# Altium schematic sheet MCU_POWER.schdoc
size 297 x 209 mm; Symbol: Drawing-Symbol_A4; Company: 嘉立创EDA; Version: V1.0; Page Size: A4; @Project Name: 西柚在学EtherCAT; @Update Date: 2026-07-29; @Create Date: 2026-07-29; Device: Drawing-Symbol_A4; @Board Name: Board1; @Page Name: P1; @Create Time: 01:18:30; @Page Count: 1; @Page No: 1; @Schematic Name: Schematic1; @Update Time: 01:18:30; @Assembly Variant: Basic; Border: 1; Title Block Position: 3; Size: A4; Width: 1170; Height: 825; Region Start: 1; X Region Count: 6; Y Region Count: 4; Blade Width: 10
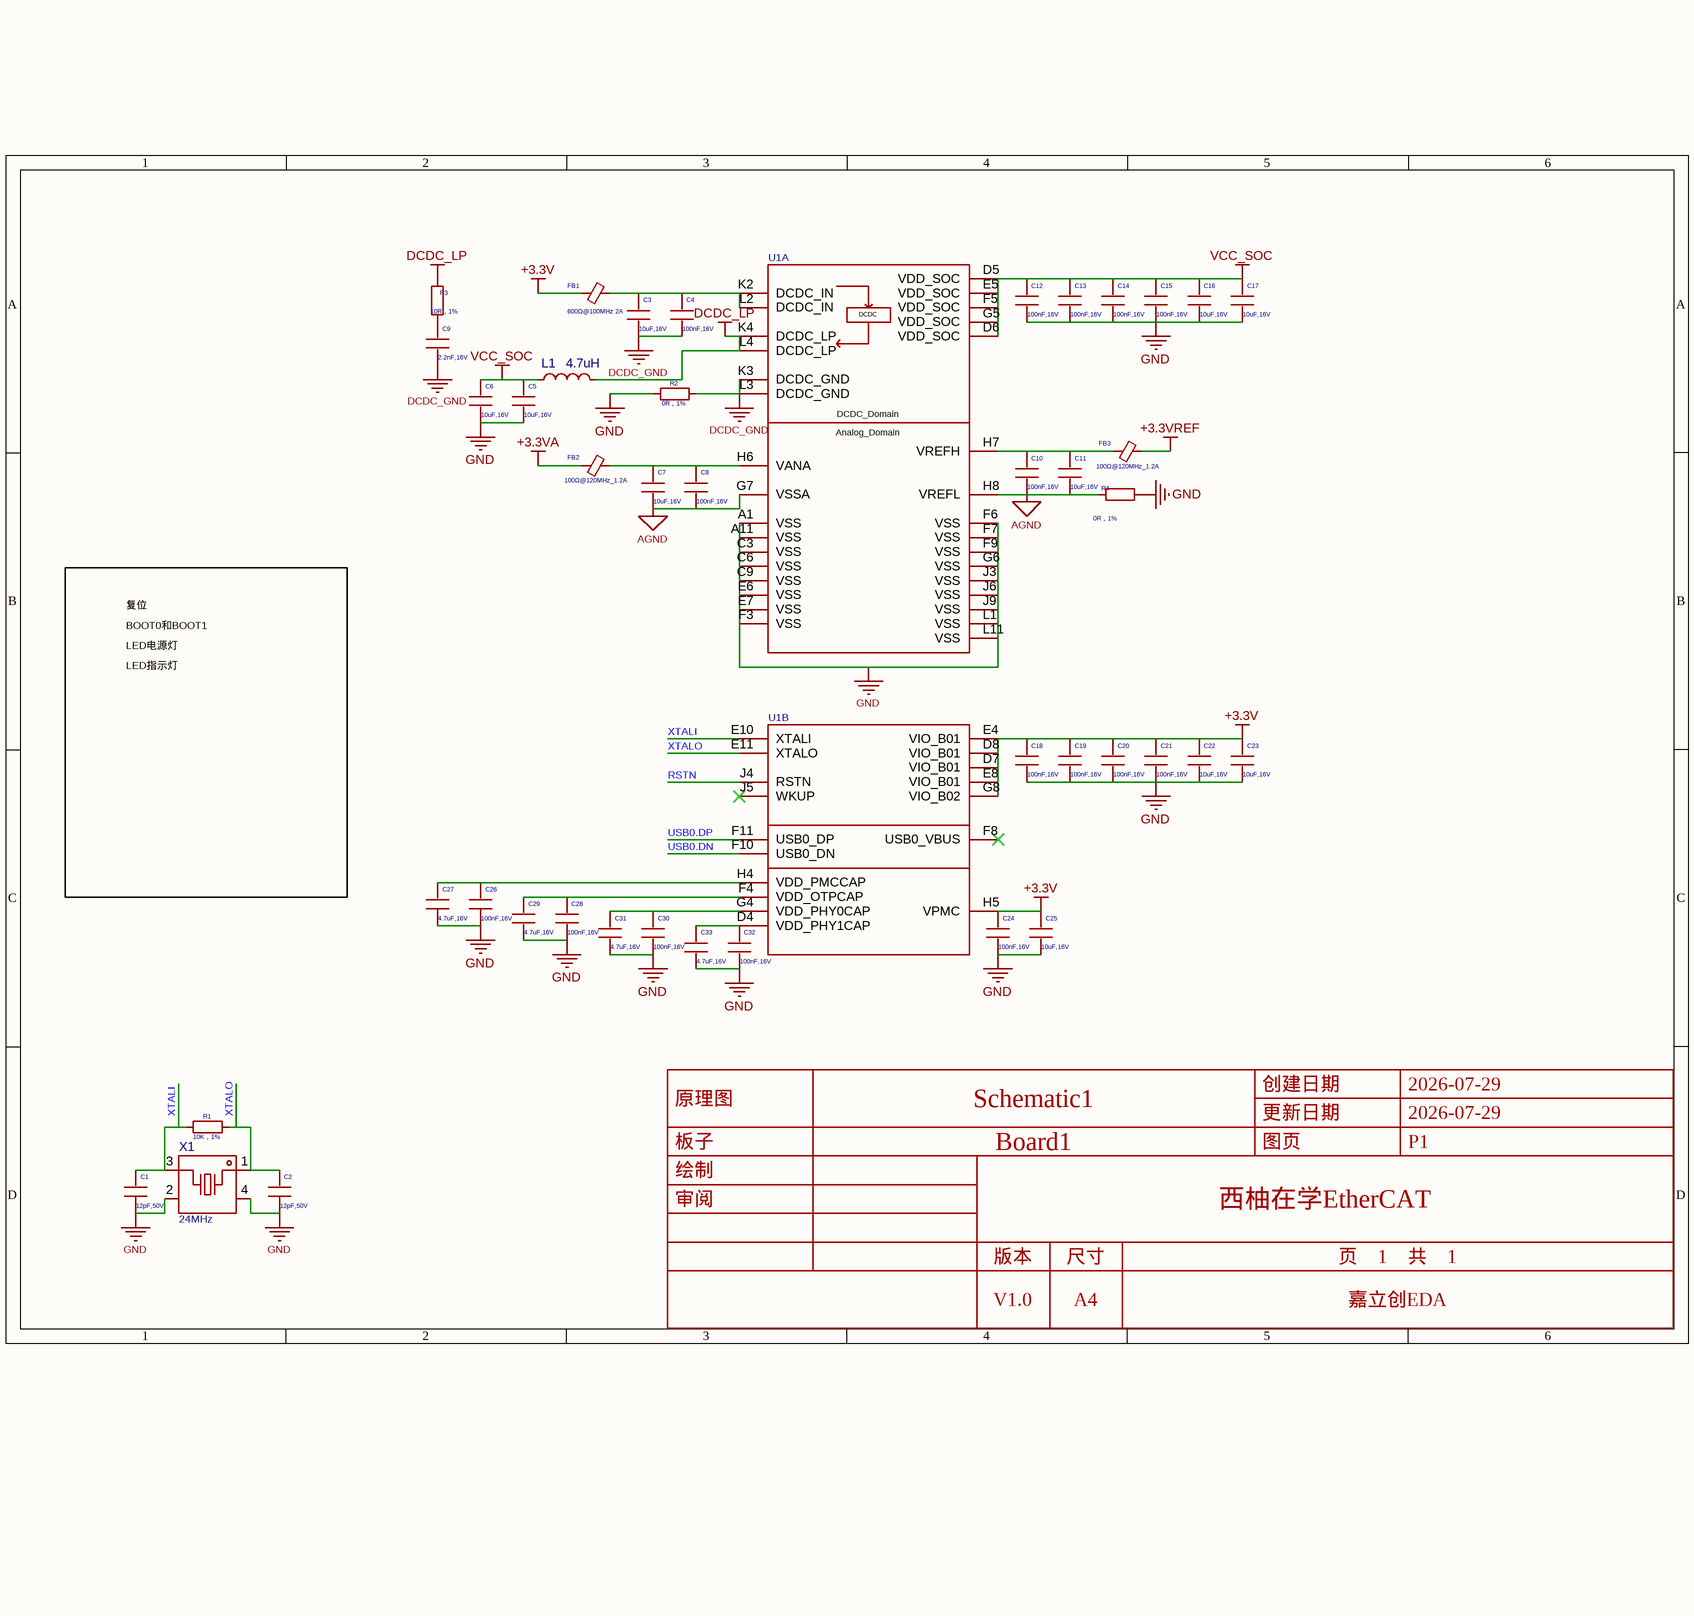
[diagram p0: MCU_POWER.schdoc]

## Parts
C1  value 12pF,50V  [03_HPM_Capacitance:C_0402_1005Metric]
C2  value 12pF,50V  [03_HPM_Capacitance:C_0402_1005Metric]
C3  value 10uF,16V  [03_HPM_Capacitance:C_0402_1005Metric]
C4  value 100nF,16V  [03_HPM_Capacitance:C_0402_1005Metric]
C5  value 10uF,16V  [03_HPM_Capacitance:C_0402_1005Metric]
C6  value 10uF,16V  [03_HPM_Capacitance:C_0402_1005Metric]
C7  value 10uF,16V  [03_HPM_Capacitance:C_0402_1005Metric]
C8  value 100nF,16V  [03_HPM_Capacitance:C_0402_1005Metric]
C9  value 2.2nF,16V  [03_HPM_Capacitance:C_0402_1005Metric]
C10  value 100nF,16V  [03_HPM_Capacitance:C_0402_1005Metric]
C11  value 10uF,16V  [03_HPM_Capacitance:C_0402_1005Metric]
C12  value 100nF,16V  [03_HPM_Capacitance:C_0402_1005Metric]
C13  value 100nF,16V  [03_HPM_Capacitance:C_0402_1005Metric]
C14  value 100nF,16V  [03_HPM_Capacitance:C_0402_1005Metric]
C15  value 100nF,16V  [03_HPM_Capacitance:C_0402_1005Metric]
C16  value 10uF,16V  [03_HPM_Capacitance:C_0402_1005Metric]
C17  value 10uF,16V  [03_HPM_Capacitance:C_0402_1005Metric]
C18  value 100nF,16V  [03_HPM_Capacitance:C_0402_1005Metric]
C19  value 100nF,16V  [03_HPM_Capacitance:C_0402_1005Metric]
C20  value 100nF,16V  [03_HPM_Capacitance:C_0402_1005Metric]
C21  value 100nF,16V  [03_HPM_Capacitance:C_0402_1005Metric]
C22  value 10uF,16V  [03_HPM_Capacitance:C_0402_1005Metric]
C23  value 10uF,16V  [03_HPM_Capacitance:C_0402_1005Metric]
C24  value 100nF,16V  [03_HPM_Capacitance:C_0402_1005Metric]
C25  value 10uF,16V  [03_HPM_Capacitance:C_0402_1005Metric]
C26  value 100nF,16V  [03_HPM_Capacitance:C_0402_1005Metric]
C27  value 4.7uF,16V  [03_HPM_Capacitance:C_0402_1005Metric]
C28  value 100nF,16V  [03_HPM_Capacitance:C_0402_1005Metric]
C29  value 4.7uF,16V  [03_HPM_Capacitance:C_0402_1005Metric]
C30  value 100nF,16V  [03_HPM_Capacitance:C_0402_1005Metric]
C31  value 4.7uF,16V  [03_HPM_Capacitance:C_0402_1005Metric]
C32  value 100nF,16V  [03_HPM_Capacitance:C_0402_1005Metric]
C33  value 4.7uF,16V  [03_HPM_Capacitance:C_0402_1005Metric]
FB1  value 600Ω@100MHz 2A  [02_HPM_Resistor:R_0603_1608Metric]
FB2  100Ω@120MHz_1.2A  [02_HPM_Resistor:R_0402_1005Metric]
FB3  100Ω@120MHz_1.2A  [02_HPM_Resistor:R_0402_1005Metric]
L1  4.7uH  [IND-SMD_L2.5-W2.0-VLS252012CX-150M]
R1  value 10K，1%  [02_HPM_Resistor:R_0402_1005Metric]
R2  value 0R，1%  [02_HPM_Resistor:R_0402_1005Metric]
R3  value 10R，1%  [02_HPM_Resistor:R_0402_1005Metric]
R4  value 0R，1%  [02_HPM_Resistor:R_0402_1005Metric]
U1  (no value)  [CABGA-121_L9.0-W9.0-R11-C11-P0.80-TL]  (parts A,B of 7)
X1  24MHz  [CRYSTAL-SMD_4P-L2.0-W1.6-BL-A]

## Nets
+3.3V: C18.1 C19.1 C20.1 C21.1 C22.1 C23.1 C24.1 C25.1 FB1.2 U1.D7(VIO_B01) U1.D8(VIO_B01) U1.E4(VIO_B01) U1.E8(VIO_B01) U1.G8(VIO_B02) U1.H5(VPMC)
+3.3VA: FB2.2
+3.3VREF: FB3.1
AGND: C7.2 C8.2 C10.2 C11.2 R4.2 U1.G7(VSSA) U1.H8(VREFL)
DCDC_GND: C3.2 C4.2 C9.2 R2.2 U1.K3(DCDC_GND) U1.L3(DCDC_GND)
DCDC_LP: L1.2 R3.2 U1.K4(DCDC_LP) U1.L4(DCDC_LP)
GND: C1.2 C2.2 C5.2 C6.2 C12.2 C13.2 C14.2 C15.2 C16.2 C17.2 C18.2 C19.2 C20.2 C21.2 C22.2 C23.2 C24.2 C25.2 C26.2 C27.2 C28.2 C29.2 C30.2 C31.2 C32.2 C33.2 R2.1 R4.1 U1.A1(VSS) U1.A11(VSS) U1.C3(VSS) U1.C6(VSS) U1.C9(VSS) U1.E6(VSS) U1.E7(VSS) U1.F3(VSS) U1.F6(VSS) U1.F7(VSS) U1.F9(VSS) U1.G6(VSS) U1.J3(VSS) U1.J6(VSS) U1.J9(VSS) U1.L1(VSS) U1.L11(VSS) X1.2(GND) X1.4(GND)
VCC_SOC: C5.1 C6.1 C12.1 C13.1 C14.1 C15.1 C16.1 C17.1 L1.1 U1.D5(VDD_SOC) U1.D6(VDD_SOC) U1.E5(VDD_SOC) U1.F5(VDD_SOC) U1.G5(VDD_SOC)
RSTN: U1.J4(RSTN)
USB0.DN: U1.F10(USB0_DN)
USB0.DP: U1.F11(USB0_DP)
XTALI: C1.1 R1.1 U1.E10(XTALI) X1.3
XTALO: C2.1 R1.2 U1.E11(XTALO) X1.1
NetC3_1: C3.1 C4.1 FB1.1 U1.K2(DCDC_IN) U1.L2(DCDC_IN)
NetC7_1: C7.1 C8.1 FB2.1 U1.H6(VANA)
NetC9_1: C9.1 R3.1
NetC10_1: C10.1 C11.1 FB3.2 U1.H7(VREFH)
NetC26_1: C26.1 C27.1 U1.H4(VDD_PMCCAP)
NetC28_1: C28.1 C29.1 U1.F4(VDD_OTPCAP)
NetC30_1: C30.1 C31.1 U1.G4(VDD_PHY0CAP)
NetC32_1: C32.1 C33.1 U1.D4(VDD_PHY1CAP)

Not connected (* = marked no-connect by the designer): U1 F8(USB0_VBUS)* J5(WKUP)*

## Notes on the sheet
- 复位
- BOOT0和BOOT1
- LED电源灯
- LED指示灯

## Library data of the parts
C1 = 电容0402: Model: CL05B104KO5NNNC; Company: SAMSUNG(三星); AddInBom: yes; ki_keywords: cap capacitor; ki_description: 0402; ki_fp_filters: C_*; UniqueId: gge80; ID: $1I27; ModelId: 222a10e09e6e477a9f85628e277082cb0819f05c4eef4c71ace90d822a990e87; ModelName: C0402; ModelTransform: 39.37,19.685,19.685,0,0,0,0,0,0
C2 = 电容0402: Model: CL05B104KO5NNNC; Company: SAMSUNG(三星); AddInBom: yes; ki_keywords: cap capacitor; ki_description: 0402; ki_fp_filters: C_*; UniqueId: gge81; ID: $1I27; ModelId: 222a10e09e6e477a9f85628e277082cb0819f05c4eef4c71ace90d822a990e87; ModelName: C0402; ModelTransform: 39.37,19.685,19.685,0,0,0,0,0,0
C3 = 电容0402: Model: CL05B104KO5NNNC; Company: SAMSUNG(三星); ki_keywords: cap capacitor; ki_description: 0402; ki_fp_filters: C_*; ID: $1I27; 3D Model: 222a10e09e6e477a9f85628e277082cb0819f05c4eef4c71ace90d822a990e87; 3D Model Transform: 39.37,19.685,19.685,0,0,0,0,0,0; AddInBom: yes; UniqueId: b3e980a047527b8f_12; ModelName: C0402
C4 = 电容0402: Model: CL05B104KO5NNNC; Company: SAMSUNG(三星); ki_keywords: cap capacitor; ki_description: 0402; ki_fp_filters: C_*; ID: $1I27; 3D Model: 222a10e09e6e477a9f85628e277082cb0819f05c4eef4c71ace90d822a990e87; 3D Model Transform: 39.37,19.685,19.685,0,0,0,0,0,0; AddInBom: yes; UniqueId: gge83; ModelName: C0402
C5 = 电容0402: Model: CL05B104KO5NNNC; Company: SAMSUNG(三星); ki_keywords: cap capacitor; ki_description: 0402; ki_fp_filters: C_*; ID: $1I27; 3D Model: 222a10e09e6e477a9f85628e277082cb0819f05c4eef4c71ace90d822a990e87; 3D Model Transform: 39.37,19.685,19.685,0,0,0,0,0,0; AddInBom: yes; UniqueId: b3e980a047527b8f_13; ModelName: C0402
C6 = 电容0402: Model: CL05B104KO5NNNC; Company: SAMSUNG(三星); ki_keywords: cap capacitor; ki_description: 0402; ki_fp_filters: C_*; ID: $1I27; 3D Model: 222a10e09e6e477a9f85628e277082cb0819f05c4eef4c71ace90d822a990e87; 3D Model Transform: 39.37,19.685,19.685,0,0,0,0,0,0; AddInBom: yes; UniqueId: b3e980a047527b8f_14; ModelName: C0402
C7 = 电容0402: Model: CL05B104KO5NNNC; Company: SAMSUNG(三星); ki_keywords: cap capacitor; ki_description: 0402; ki_fp_filters: C_*; ID: $1I27; 3D Model: 222a10e09e6e477a9f85628e277082cb0819f05c4eef4c71ace90d822a990e87; 3D Model Transform: 39.37,19.685,19.685,0,0,0,0,0,0; AddInBom: yes; UniqueId: b3e980a047527b8f_15; ModelName: C0402
C8 = 电容0402: Model: CL05B104KO5NNNC; Company: SAMSUNG(三星); ki_keywords: cap capacitor; ki_description: 0402; ki_fp_filters: C_*; ID: $1I27; 3D Model: 222a10e09e6e477a9f85628e277082cb0819f05c4eef4c71ace90d822a990e87; 3D Model Transform: 39.37,19.685,19.685,0,0,0,0,0,0; AddInBom: yes; UniqueId: gge83_0; ModelName: C0402
C9 = 电容0402: Model: CL05B104KO5NNNC; Company: SAMSUNG(三星); ki_keywords: cap capacitor; ki_description: 0402; ki_fp_filters: C_*; ID: $1I27; 3D Model: 222a10e09e6e477a9f85628e277082cb0819f05c4eef4c71ace90d822a990e87; 3D Model Transform: 39.37,19.685,19.685,0,0,0,0,0,0; AddInBom: yes; UniqueId: gge83_1; ModelName: C0402
C10 = 电容0402: Model: CL05B104KO5NNNC; Company: SAMSUNG(三星); ki_keywords: cap capacitor; ki_description: 0402; ki_fp_filters: C_*; ID: $1I27; 3D Model: 222a10e09e6e477a9f85628e277082cb0819f05c4eef4c71ace90d822a990e87; 3D Model Transform: 39.37,19.685,19.685,0,0,0,0,0,0; AddInBom: yes; UniqueId: gge83_2; ModelName: C0402
C11 = 电容0402: Model: CL05B104KO5NNNC; Company: SAMSUNG(三星); ki_keywords: cap capacitor; ki_description: 0402; ki_fp_filters: C_*; ID: $1I27; 3D Model: 222a10e09e6e477a9f85628e277082cb0819f05c4eef4c71ace90d822a990e87; 3D Model Transform: 39.37,19.685,19.685,0,0,0,0,0,0; AddInBom: yes; UniqueId: b3e980a047527b8f_16; ModelName: C0402
C12 = 电容0402: Model: CL05B104KO5NNNC; Company: SAMSUNG(三星); ki_keywords: cap capacitor; ki_description: 0402; ki_fp_filters: C_*; ID: $1I27; 3D Model: 222a10e09e6e477a9f85628e277082cb0819f05c4eef4c71ace90d822a990e87; 3D Model Transform: 39.37,19.685,19.685,0,0,0,0,0,0; AddInBom: yes; UniqueId: gge83_3; ModelName: C0402
C13 = 电容0402: Model: CL05B104KO5NNNC; Company: SAMSUNG(三星); ki_keywords: cap capacitor; ki_description: 0402; ki_fp_filters: C_*; ID: $1I27; 3D Model: 222a10e09e6e477a9f85628e277082cb0819f05c4eef4c71ace90d822a990e87; 3D Model Transform: 39.37,19.685,19.685,0,0,0,0,0,0; AddInBom: yes; UniqueId: gge83_4; ModelName: C0402
C14 = 电容0402: Model: CL05B104KO5NNNC; Company: SAMSUNG(三星); ki_keywords: cap capacitor; ki_description: 0402; ki_fp_filters: C_*; ID: $1I27; 3D Model: 222a10e09e6e477a9f85628e277082cb0819f05c4eef4c71ace90d822a990e87; 3D Model Transform: 39.37,19.685,19.685,0,0,0,0,0,0; AddInBom: yes; UniqueId: gge83_5; ModelName: C0402
C15 = 电容0402: Model: CL05B104KO5NNNC; Company: SAMSUNG(三星); ki_keywords: cap capacitor; ki_description: 0402; ki_fp_filters: C_*; ID: $1I27; 3D Model: 222a10e09e6e477a9f85628e277082cb0819f05c4eef4c71ace90d822a990e87; 3D Model Transform: 39.37,19.685,19.685,0,0,0,0,0,0; AddInBom: yes; UniqueId: gge83_6; ModelName: C0402
C16 = 电容0402: Model: CL05B104KO5NNNC; Company: SAMSUNG(三星); ki_keywords: cap capacitor; ki_description: 0402; ki_fp_filters: C_*; ID: $1I27; 3D Model: 222a10e09e6e477a9f85628e277082cb0819f05c4eef4c71ace90d822a990e87; 3D Model Transform: 39.37,19.685,19.685,0,0,0,0,0,0; AddInBom: yes; UniqueId: b3e980a047527b8f_17; ModelName: C0402
C17 = 电容0402: Model: CL05B104KO5NNNC; Company: SAMSUNG(三星); ki_keywords: cap capacitor; ki_description: 0402; ki_fp_filters: C_*; ID: $1I27; 3D Model: 222a10e09e6e477a9f85628e277082cb0819f05c4eef4c71ace90d822a990e87; 3D Model Transform: 39.37,19.685,19.685,0,0,0,0,0,0; AddInBom: yes; UniqueId: b3e980a047527b8f_18; ModelName: C0402
C18 = 电容0402: Model: CL05B104KO5NNNC; Company: SAMSUNG(三星); ki_keywords: cap capacitor; ki_description: 0402; ki_fp_filters: C_*; ID: $1I27; 3D Model: 222a10e09e6e477a9f85628e277082cb0819f05c4eef4c71ace90d822a990e87; 3D Model Transform: 39.37,19.685,19.685,0,0,0,0,0,0; AddInBom: yes; UniqueId: gge83_7; ModelName: C0402
C19 = 电容0402: Model: CL05B104KO5NNNC; Company: SAMSUNG(三星); ki_keywords: cap capacitor; ki_description: 0402; ki_fp_filters: C_*; ID: $1I27; 3D Model: 222a10e09e6e477a9f85628e277082cb0819f05c4eef4c71ace90d822a990e87; 3D Model Transform: 39.37,19.685,19.685,0,0,0,0,0,0; AddInBom: yes; UniqueId: gge83_8; ModelName: C0402
C20 = 电容0402: Model: CL05B104KO5NNNC; Company: SAMSUNG(三星); ki_keywords: cap capacitor; ki_description: 0402; ki_fp_filters: C_*; ID: $1I27; 3D Model: 222a10e09e6e477a9f85628e277082cb0819f05c4eef4c71ace90d822a990e87; 3D Model Transform: 39.37,19.685,19.685,0,0,0,0,0,0; AddInBom: yes; UniqueId: gge83_9; ModelName: C0402
C21 = 电容0402: Model: CL05B104KO5NNNC; Company: SAMSUNG(三星); ki_keywords: cap capacitor; ki_description: 0402; ki_fp_filters: C_*; ID: $1I27; 3D Model: 222a10e09e6e477a9f85628e277082cb0819f05c4eef4c71ace90d822a990e87; 3D Model Transform: 39.37,19.685,19.685,0,0,0,0,0,0; AddInBom: yes; UniqueId: gge83_10; ModelName: C0402
C22 = 电容0402: Model: CL05B104KO5NNNC; Company: SAMSUNG(三星); ki_keywords: cap capacitor; ki_description: 0402; ki_fp_filters: C_*; ID: $1I27; 3D Model: 222a10e09e6e477a9f85628e277082cb0819f05c4eef4c71ace90d822a990e87; 3D Model Transform: 39.37,19.685,19.685,0,0,0,0,0,0; AddInBom: yes; UniqueId: b3e980a047527b8f_19; ModelName: C0402
C23 = 电容0402: Model: CL05B104KO5NNNC; Company: SAMSUNG(三星); ki_keywords: cap capacitor; ki_description: 0402; ki_fp_filters: C_*; ID: $1I27; 3D Model: 222a10e09e6e477a9f85628e277082cb0819f05c4eef4c71ace90d822a990e87; 3D Model Transform: 39.37,19.685,19.685,0,0,0,0,0,0; AddInBom: yes; UniqueId: b3e980a047527b8f_20; ModelName: C0402
C24 = 电容0402: Model: CL05B104KO5NNNC; Company: SAMSUNG(三星); ki_keywords: cap capacitor; ki_description: 0402; ki_fp_filters: C_*; ID: $1I27; 3D Model: 222a10e09e6e477a9f85628e277082cb0819f05c4eef4c71ace90d822a990e87; 3D Model Transform: 39.37,19.685,19.685,0,0,0,0,0,0; AddInBom: yes; UniqueId: gge83_11; ModelName: C0402
C25 = 电容0402: Model: CL05B104KO5NNNC; Company: SAMSUNG(三星); ki_keywords: cap capacitor; ki_description: 0402; ki_fp_filters: C_*; ID: $1I27; 3D Model: 222a10e09e6e477a9f85628e277082cb0819f05c4eef4c71ace90d822a990e87; 3D Model Transform: 39.37,19.685,19.685,0,0,0,0,0,0; AddInBom: yes; UniqueId: b3e980a047527b8f_21; ModelName: C0402
C26 = 电容0402: Model: CL05B104KO5NNNC; Company: SAMSUNG(三星); ki_keywords: cap capacitor; ki_description: 0402; ki_fp_filters: C_*; ID: $1I27; 3D Model: 222a10e09e6e477a9f85628e277082cb0819f05c4eef4c71ace90d822a990e87; 3D Model Transform: 39.37,19.685,19.685,0,0,0,0,0,0; AddInBom: yes; UniqueId: gge83_12; ModelName: C0402
C27 = 电容0402: Model: CL05B104KO5NNNC; Company: SAMSUNG(三星); ki_keywords: cap capacitor; ki_description: 0402; ki_fp_filters: C_*; ID: $1I27; 3D Model: 222a10e09e6e477a9f85628e277082cb0819f05c4eef4c71ace90d822a990e87; 3D Model Transform: 39.37,19.685,19.685,0,0,0,0,0,0; AddInBom: yes; UniqueId: b3e980a047527b8f_22; ModelName: C0402
C28 = 电容0402: Model: CL05B104KO5NNNC; Company: SAMSUNG(三星); ki_keywords: cap capacitor; ki_description: 0402; ki_fp_filters: C_*; ID: $1I27; 3D Model: 222a10e09e6e477a9f85628e277082cb0819f05c4eef4c71ace90d822a990e87; 3D Model Transform: 39.37,19.685,19.685,0,0,0,0,0,0; AddInBom: yes; UniqueId: gge83_13; ModelName: C0402
C29 = 电容0402: Model: CL05B104KO5NNNC; Company: SAMSUNG(三星); ki_keywords: cap capacitor; ki_description: 0402; ki_fp_filters: C_*; ID: $1I27; 3D Model: 222a10e09e6e477a9f85628e277082cb0819f05c4eef4c71ace90d822a990e87; 3D Model Transform: 39.37,19.685,19.685,0,0,0,0,0,0; AddInBom: yes; UniqueId: b3e980a047527b8f_23; ModelName: C0402
C30 = 电容0402: Model: CL05B104KO5NNNC; Company: SAMSUNG(三星); ki_keywords: cap capacitor; ki_description: 0402; ki_fp_filters: C_*; ID: $1I27; 3D Model: 222a10e09e6e477a9f85628e277082cb0819f05c4eef4c71ace90d822a990e87; 3D Model Transform: 39.37,19.685,19.685,0,0,0,0,0,0; AddInBom: yes; UniqueId: gge83_14; ModelName: C0402
C31 = 电容0402: Model: CL05B104KO5NNNC; Company: SAMSUNG(三星); ki_keywords: cap capacitor; ki_description: 0402; ki_fp_filters: C_*; ID: $1I27; 3D Model: 222a10e09e6e477a9f85628e277082cb0819f05c4eef4c71ace90d822a990e87; 3D Model Transform: 39.37,19.685,19.685,0,0,0,0,0,0; AddInBom: yes; UniqueId: b3e980a047527b8f_24; ModelName: C0402
C32 = 电容0402: Model: CL05B104KO5NNNC; Company: SAMSUNG(三星); ki_keywords: cap capacitor; ki_description: 0402; ki_fp_filters: C_*; ID: $1I27; 3D Model: 222a10e09e6e477a9f85628e277082cb0819f05c4eef4c71ace90d822a990e87; 3D Model Transform: 39.37,19.685,19.685,0,0,0,0,0,0; AddInBom: yes; UniqueId: gge83_15; ModelName: C0402
C33 = 电容0402: Model: CL05B104KO5NNNC; Company: SAMSUNG(三星); ki_keywords: cap capacitor; ki_description: 0402; ki_fp_filters: C_*; ID: $1I27; 3D Model: 222a10e09e6e477a9f85628e277082cb0819f05c4eef4c71ace90d822a990e87; 3D Model Transform: 39.37,19.685,19.685,0,0,0,0,0,0; AddInBom: yes; UniqueId: b3e980a047527b8f_25; ModelName: C0402
FB1 = BLM18KG6001SN1D: Model: PZ1608D101-2R0TF; Company: Sunlord(顺络); Sheetfile: 09.POWER.kicad_sch; Sheetname: 09.POWER; ki_description: Resistor; AddInBom: yes; ki_fp_filters: Inductor_* L_* *Ferrite*; UniqueId: gge1040; ID: $3I45; ki_keywords: R res resistor; ModelId: 3281a289d46d4bb1877be1eabd090e130819f05c4eef4c71ace90d822a990e87; ModelName: R0603_L1.6-W0.8-H0.8; ModelTransform: 62.992000938653945,31.496000469326972,31.496000469326972,0,0,0,0,0,0
FB2 FB3 = BLM15PD121SN1D: AddInBom: yes; ModelId: 671aefced39d4c318694bba8bd8efd390819f05c4eef4c71ace90d822a990e87; ModelName: R0402_L1.0-W0.5-H0.5; ModelTransform: 39.37,19.685,19.685,0,0,0,0,0,0
L1 = FTC252010S4R7MBCA: Manufacturer: cjiang(长江微电); Tolerance: ±20%; Rated Current: 2A; Saturation Current (Isat): 2.6A; DC Resistance (DCR): 160mΩ; Type: 一体成型电感; 3D Model: e143e04106934774881cec608355723f; 3D Model Transform: 98.504,78.819,0,0,0,0,-0.004,-0.003,0; AddInBom: yes
R1 = 电阻0402: Model: 0402WGF1002TCE; Company: UNI-ROYAL(厚声); AddInBom: yes; ki_keywords: R res resistor; ki_description: Resistor; ki_fp_filters: R_*; UniqueId: gge82; ID: $3I57; ModelId: 98c88bc2b9094f218f3a3e30a70127380819f05c4eef4c71ace90d822a990e87; ModelName: R0402_L1.0-W0.5-H0.4; ModelTransform: 39.37,19.685,14.173200563192367,0,0,0,0,0,0
R2 = 电阻0402: Model: 0402WGF1002TCE; Company: UNI-ROYAL(厚声); ki_keywords: R res resistor; ki_description: Resistor; ki_fp_filters: R_*; ID: $3I57; 3D Model: 98c88bc2b9094f218f3a3e30a70127380819f05c4eef4c71ace90d822a990e87; 3D Model Transform: 39.37,19.685,14.173200563192367,0,0,0,0,0,0; AddInBom: yes; UniqueId: 469542c170a520e3_0; ModelName: R0402_L1.0-W0.5-H0.4
R3 = 电阻0402: Model: 0402WGF1002TCE; Company: UNI-ROYAL(厚声); ki_keywords: R res resistor; ki_description: Resistor; ki_fp_filters: R_*; ID: $3I57; 3D Model: 98c88bc2b9094f218f3a3e30a70127380819f05c4eef4c71ace90d822a990e87; 3D Model Transform: 39.37,19.685,14.173200563192367,0,0,0,0,0,0; AddInBom: yes; UniqueId: 469542c170a520e3_1; ModelName: R0402_L1.0-W0.5-H0.4
R4 = 电阻0402: Model: 0402WGF1002TCE; Company: UNI-ROYAL(厚声); ki_keywords: R res resistor; ki_description: Resistor; ki_fp_filters: R_*; ID: $3I57; 3D Model: 98c88bc2b9094f218f3a3e30a70127380819f05c4eef4c71ace90d822a990e87; 3D Model Transform: 39.37,19.685,14.173200563192367,0,0,0,0,0,0; AddInBom: yes; UniqueId: 469542c170a520e3_2; ModelName: R0402_L1.0-W0.5-H0.4
U1 = HPM5E3YIVK: Relevance: []; AddInBom: yes; ModelId: dd144502655a43d48ea393b0a7eceb850819f05c4eef4c71ace90d822a990e87; ModelTransform: 354.33,354.33,41.33850046932697,0,0,0,0,0,0
X1 = 晶振2016: Manufacturer: YXC(扬兴晶振); ManufacturerPart: XL7EL89CKI-111YLC-24M; Normal temperature Frequency Tolerance: ±10ppm; Load Capacitance: 8pF; Frequency Stability: ±20ppm; AddInBom: yes; UniqueId: gge1092; ID: $1I86; ModelId: 3c7217722bdc4daeae1fd6f7f164cfcf0819f05c4eef4c71ace90d822a990e87; ModelName: CRYSTAL-SMD_4P-L2.0-W1.6-BL-2; ModelTransform: 78.74,62.992000938653945,18.110199521873145,0,0,0,0,0,0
